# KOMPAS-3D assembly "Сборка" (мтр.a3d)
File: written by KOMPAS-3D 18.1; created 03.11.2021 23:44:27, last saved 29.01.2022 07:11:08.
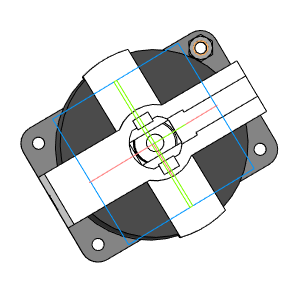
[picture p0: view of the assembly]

Document properties: Автор: 111; Полное имя файла: C:\Users\admin\Desktop\ffb\мтр.a3d

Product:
- Part/product: Сборка
    Масса: 2.28522
  - Component [detail]: Деталь  | pos. 5  | Масса: 2.13673; Раздел спецификации: Детали; source file: motor.m3d
  - Component [detail]: Деталь  | pos. 2  | Масса: 0.0584065; Раздел спецификации: Детали; source file: magnit.m3d
  - Component [detail]: PANEL-MOTOR_default  | pos. 4  | Масса: 0.0800166; Раздел спецификации: Детали; source file: PANEL-MOTOR.m3d
  - Component [standard]: Гайка М5-6H.LF ГОСТ Р 50273-92  | pos. 6  | Масса: 0.00208392; Раздел спецификации: Стандартные изделия; Рассекать на разрезах: no
  - Component [detail]: Деталь  | pos. 7  | Материал: Пенопласт ПЭ-2  ТУ В-172-70 (density 270 kg/m3); Масса: 0.00798896; Раздел спецификации: Детали; source file: ddd1.m3d

Referenced files in C:\Users\admin\Desktop\ffb\: magnit.m3d, PANEL-MOTOR.m3d, motor.m3d, ddd1.m3d
Referenced files in C:\Program Files\ASCON\KOMPAS-3D v18\Libs\PARTLib\DATA\vault\Methods\Kompas\3D\: PLib_Nut_ISO_1100.m3d
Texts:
  Крепежное изделие ГОСТ
  bcut1
  hole1
  hcut1
  r1pt
  hole2
  cut1
  cut2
